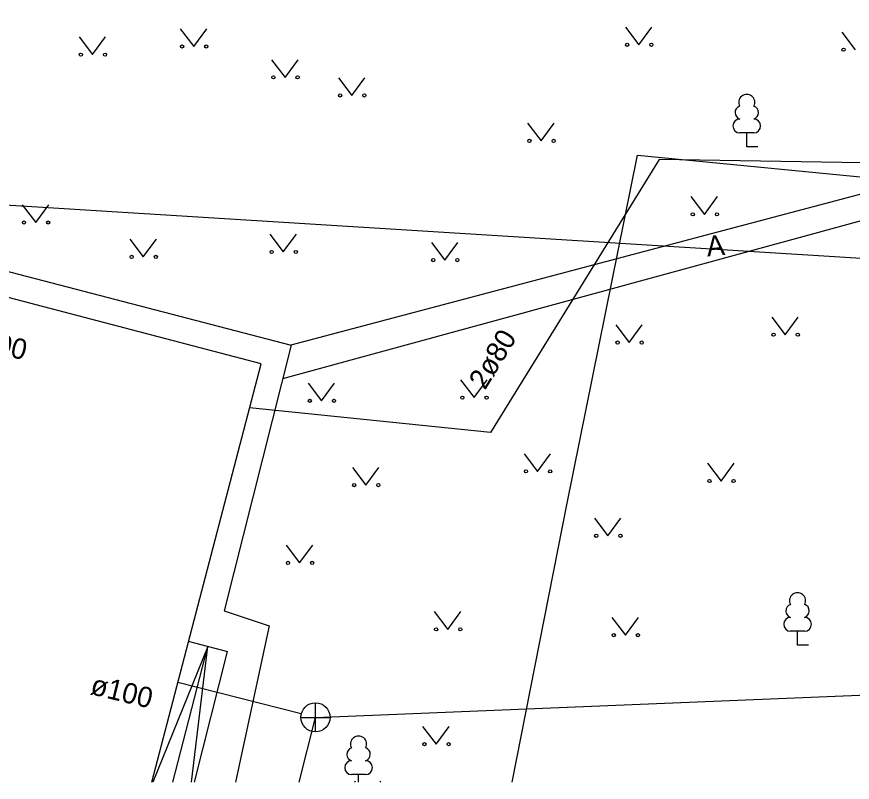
# Model space of a CAD drawing. Extents: x 714391 to 714584, y 6589993 to 6590151.
# Drawn here: x 714428.09 to 714456.74, y 6589992.71 to 6590018.98 of the extents above; entities that cross this region are included whole.
import ezdxf

# ---------------------------------------------------------------- set-up
doc = ezdxf.new("R2010")
doc.units = 0
for name, color, linetype in [('HALJASTUS', 7, 'Continuous'), ('HOONE', 7, 'Continuous'), ('KKAEV', 7, 'Continuous'), ('KTRASS', 7, 'Continuous'), ('MPKAABEL', 7, 'Continuous'), ('PUU', 7, 'Continuous'), ('TEE', 7, 'Continuous'), ('TORU NR', 7, 'Continuous'), ('TTRASS', 7, 'Continuous'), ('Слой 1', 7, 'Continuous')]:
    doc.layers.add(name, color=color, linetype=linetype)

msp = doc.modelspace()

# ---------------------------------------------------------------- linework, layer by layer
at = {"layer": 'HALJASTUS'}
for p, q in [((714433.697, 6590018.567), (714434.16, 6590017.96)), ((714434.16, 6590017.96), (714434.606, 6590018.567)), ((714448.957, 6590018.627), (714449.42, 6590018.02)), ((714449.42, 6590018.02), (714449.866, 6590018.627)), ((714456.377, 6590018.457), (714456.84, 6590017.85)), ((714430.227, 6590018.287), (714430.69, 6590017.68)), ((714430.69, 6590017.68), (714431.136, 6590018.287)), ((714436.827, 6590017.507), (714437.29, 6590016.9)), ((714437.29, 6590016.9), (714437.736, 6590017.507)), ((714439.117, 6590016.887), (714439.58, 6590016.28)), ((714439.58, 6590016.28), (714440.026, 6590016.887)), ((714445.607, 6590015.327), (714446.07, 6590014.72)), ((714446.07, 6590014.72), (714446.516, 6590015.327)), ((714451.207, 6590012.807), (714451.67, 6590012.2)), ((714451.67, 6590012.2), (714452.116, 6590012.807)), ((714428.277, 6590012.527), (714428.74, 6590011.92)), ((714428.74, 6590011.92), (714429.186, 6590012.527)), ((714436.767, 6590011.517), (714437.23, 6590010.91)), ((714437.23, 6590010.91), (714437.676, 6590011.517)), ((714431.967, 6590011.347), (714432.43, 6590010.74)), ((714432.43, 6590010.74), (714432.876, 6590011.347)), ((714442.307, 6590011.237), (714442.77, 6590010.63)), ((714442.77, 6590010.63), (714443.216, 6590011.237)), ((714453.977, 6590008.677), (714454.44, 6590008.07)), ((714454.44, 6590008.07), (714454.886, 6590008.677)), ((714448.627, 6590008.407), (714449.09, 6590007.8)), ((714449.09, 6590007.8), (714449.536, 6590008.407)), ((714438.077, 6590006.407), (714438.54, 6590005.8)), ((714438.54, 6590005.8), (714438.986, 6590006.407)), ((714443.307, 6590006.517), (714443.77, 6590005.91)), ((714443.77, 6590005.91), (714444.216, 6590006.517)), ((714445.487, 6590003.987), (714445.95, 6590003.38)), ((714445.95, 6590003.38), (714446.396, 6590003.987)), ((714439.597, 6590003.517), (714440.06, 6590002.91)), ((714440.06, 6590002.91), (714440.506, 6590003.517)), ((714451.777, 6590003.657), (714452.24, 6590003.05)), ((714452.24, 6590003.05), (714452.686, 6590003.657)), ((714447.897, 6590001.777), (714448.36, 6590001.17)), ((714448.36, 6590001.17), (714448.806, 6590001.777)), ((714437.327, 6590000.847), (714437.79, 6590000.24)), ((714437.79, 6590000.24), (714438.236, 6590000.847)), ((714442.407, 6589998.567), (714442.87, 6589997.96)), ((714442.87, 6589997.96), (714443.316, 6589998.567)), ((714448.497, 6589998.367), (714448.96, 6589997.76)), ((714448.96, 6589997.76), (714449.406, 6589998.367)), ((714442.007, 6589994.627), (714442.47, 6589994.02)), ((714442.47, 6589994.02), (714442.916, 6589994.627)), ((714439.667, 6589992.747), (714439.694, 6589992.711)), ((714440.549, 6589992.711), (714440.576, 6589992.747))]:
    msp.add_line(p, q, dxfattribs=at)
for centre in [(714449.019, 6590018.02), (714449.848, 6590018.02), (714433.759, 6590017.96), (714434.588, 6590017.96), (714456.439, 6590017.85), (714430.289, 6590017.68), (714431.118, 6590017.68), (714436.889, 6590016.9), (714437.718, 6590016.9), (714439.179, 6590016.28), (714440.008, 6590016.28), (714445.669, 6590014.72), (714446.498, 6590014.72), (714451.269, 6590012.2), (714452.098, 6590012.2), (714428.339, 6590011.92), (714429.168, 6590011.92), (714436.829, 6590010.91), (714437.658, 6590010.91), (714432.029, 6590010.74), (714432.858, 6590010.74), (714442.369, 6590010.63), (714443.198, 6590010.63), (714454.039, 6590008.07), (714454.868, 6590008.07), (714448.689, 6590007.8), (714449.518, 6590007.8), (714438.139, 6590005.8), (714438.968, 6590005.8), (714443.369, 6590005.91), (714444.198, 6590005.91), (714445.549, 6590003.38), (714446.378, 6590003.38), (714439.659, 6590002.91), (714440.488, 6590002.91), (714451.839, 6590003.05), (714452.668, 6590003.05), (714447.959, 6590001.17), (714448.788, 6590001.17), (714437.389, 6590000.24), (714438.218, 6590000.24), (714442.469, 6589997.96), (714443.298, 6589997.96), (714448.559, 6589997.76), (714449.388, 6589997.76), (714442.069, 6589994.02), (714442.898, 6589994.02)]:
    msp.add_circle(centre, 0.055, dxfattribs=at)
at = {"layer": 'HOONE'}
for points in [[(714432.717, 6589992.711), (714436.467, 6590007.065), (714425.957, 6590009.825)], [(714433.967, 6589997.555), (714435.317, 6589997.195)], [(714434.083, 6589992.711), (714434.647, 6589997.375), (714432.759, 6589992.711)], [(714433.443, 6589992.711), (714434.647, 6589997.375)], [(714434.188, 6589992.711), (714435.317, 6589997.195)]]:
    msp.add_lwpolyline(points, dxfattribs=at)
at = {"layer": 'KKAEV'}
for p, q in [((714438.332, 6589994.44), (714438.332, 6589995.44)), ((714437.832, 6589994.94), (714438.832, 6589994.94))]:
    msp.add_line(p, q, dxfattribs=at)
msp.add_circle((714438.332, 6589994.94), 0.5, dxfattribs=at)
at = {"layer": 'KTRASS'}
for points in [[(714437.847, 6589995.063), (714433.612, 6589996.137)], [(714438.332, 6589994.94), (714470.908, 6589996.272)], [(714437.769, 6589992.711), (714438.332, 6589994.94)]]:
    msp.add_lwpolyline(points, dxfattribs=at)
at = {"layer": 'MPKAABEL'}
msp.add_lwpolyline([(714445.074, 6589992.711), (714446.96, 6590002.29), (714449.37, 6590014.23), (714458.43, 6590013.35)], dxfattribs=at)
at = {"layer": 'PUU'}
for p, q in [((714453.36, 6590014.995), (714452.88, 6590014.995)), ((714453.12, 6590014.52), (714453.12, 6590014.995)), ((714453.5, 6590014.52), (714453.12, 6590014.52)), ((714455.1, 6589997.895), (714454.62, 6589997.895)), ((714454.86, 6589997.42), (714454.86, 6589997.895)), ((714455.24, 6589997.42), (714454.86, 6589997.42)), ((714440.05, 6589992.975), (714439.57, 6589992.975)), ((714439.81, 6589992.711), (714439.81, 6589992.975))]:
    msp.add_line(p, q, dxfattribs=at)
for centre, radius, start, end in [((714453.12, 6590016.04), 0.277, 332.5799, 207.4201), ((714452.95, 6590015.693), 0.233, 109.0217, 253.1415), ((714453.29, 6590015.693), 0.233, 286.8508, 70.9859), ((714452.883, 6590015.232), 0.238, 90.0016, 269.3953), ((714453.357, 6590015.232), 0.238, 270.6047, 89.9984), ((714454.86, 6589998.94), 0.277, 332.5799, 207.4201), ((714454.69, 6589998.593), 0.233, 109.0217, 253.1415), ((714455.03, 6589998.593), 0.233, 286.8508, 70.9859), ((714454.623, 6589998.132), 0.238, 90.0016, 269.3953), ((714455.097, 6589998.132), 0.238, 270.6047, 89.9984), ((714439.81, 6589994.02), 0.277, 332.5799, 207.4201), ((714439.64, 6589993.673), 0.233, 109.0217, 253.1415), ((714439.98, 6589993.673), 0.233, 286.8508, 70.9859), ((714439.573, 6589993.212), 0.238, 90.0016, 269.3953), ((714440.047, 6589993.212), 0.238, 270.6047, 89.9984)]:
    msp.add_arc(centre, radius, start, end, dxfattribs=at)
at = {"layer": 'TEE'}
for points in [[(714437.5, 6590007.72), (714457.52, 6590013.03), (714457.67, 6590013.43)], [(714437.21, 6590006.57), (714457.43, 6590012.09), (714458.46, 6590004.25), (714458.45, 6590003.5), (714457.7, 6590000.68), (714461.014, 6589999.801), (714462.195, 6589999.487), (714468.354, 6589997.853), (714467.989, 6589996.804), (714467.054, 6589992.711)], [(714420.637, 6589992.711), (714425.417, 6590010.855), (714437.497, 6590007.715), (714435.197, 6589998.595), (714436.747, 6589998.085), (714435.586, 6589992.711)]]:
    msp.add_lwpolyline(points, dxfattribs=at)
at = {"layer": 'TTRASS'}
msp.add_lwpolyline([(714458.46, 6590013.95), (714450.12, 6590014.08), (714444.33, 6590004.71), (714436.07, 6590005.56)], dxfattribs=at)
at = {"layer": 'Слой 1'}
msp.add_lwpolyline([(714455.78, 6590085.63), (714478.99, 6590085.97), (714478.28, 6590068.22), (714475.39, 6590009.54), (714423.1, 6590012.8)], close=True, dxfattribs=at)

# ---------------------------------------------------------------- texts
at = {"layer": 'TEE'}
msp.add_text('A', height=0.7, rotation=5.4691, dxfattribs=at).set_placement((714451.769, 6590010.752))
at = {"layer": 'TORU NR'}
for s, rotation, p in [('ø100', 346.3104, (714426.269, 6590007.695)), ('2ø80', 58.6448, (714444.144, 6590006.146)), ('ø100', 346.3104, (714430.579, 6589995.745))]:
    msp.add_text(s, height=0.7, rotation=rotation, dxfattribs=at).set_placement(p)

doc.saveas('drawing.dxf')
